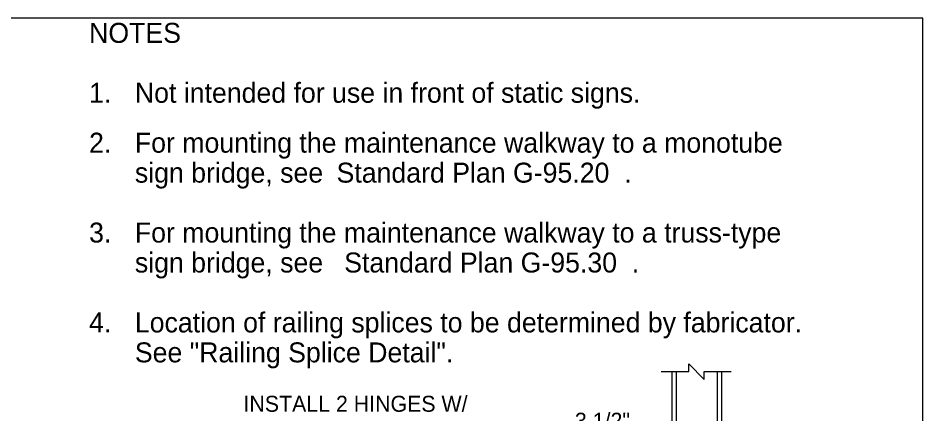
# Model space of a CAD drawing. Extents: x 99862 to 103151, y 100000 to 108076.
# Drawn here: x 102244 to 103151, y 101679 to 102076 of the extents above; entities that cross this region are included whole.
import ezdxf

# ---------------------------------------------------------------- set-up
doc = ezdxf.new("R2010")
doc.units = 0
for name, color, linetype in [('Level 1', 7, 'Continuous'), ('Level 13', 7, 'Continuous'), ('Level 15', 7, 'Continuous'), ('Level 20', 7, 'Continuous'), ('Level 4', 7, 'Continuous'), ('Level 60', 7, 'Continuous')]:
    doc.layers.add(name, color=color, linetype=linetype)

msp = doc.modelspace()

# ---------------------------------------------------------------- linework, layer by layer
at = {"layer": 'Level 1'}
msp.add_lwpolyline([(99862, 99999.5), (103151, 99999.5), (103151, 102075.5), (99862, 102075.5)], close=True, dxfattribs=at)
at = {"layer": 'Level 13'}
for p, q in [((102899.33, 101721.47), (102899.33, 101122.28)), ((102949.33, 101122.28), (102949.33, 101721.47))]:
    msp.add_line(p, q, dxfattribs=at)
at = {"layer": 'Level 15'}
msp.add_lwpolyline([(102888.69, 101721.47), (102916.27, 101721.47), (102916.27, 101729.21), (102931.76, 101713.73), (102931.76, 101721.47), (102958.68, 101721.47)], dxfattribs=at)
at = {"layer": 'Level 4'}
for p, q in [((102903.88, 101122.28), (102903.88, 101721.47)), ((102944.79, 101721.47), (102944.79, 101122.28))]:
    msp.add_line(p, q, dxfattribs=at)
at = {"layer": 'Level 60'}
msp.add_line((103151, 102075.5), (103151, 102075.5), dxfattribs=at)

# ---------------------------------------------------------------- texts
at = {"layer": 'Level 20'}
for s, height, p in [('NOTES', 20, (102314.91, 102050.74)), ('1.', 20, (102314.91, 101990.74)), ('Not intended for use in front of static signs.', 20, (102360.82, 101990.74)), ('2.', 20, (102314.91, 101940.74)), ('For mounting the maintenance walkway to a monotube', 20, (102360.82, 101940.74)), ('sign bridge, see', 20, (102360.82, 101910.74)), (' Standard Plan G-95.20', 20, (102555.62, 101910.74)), ('.', 20, (102851.54, 101910.74)), ('3.', 20, (102314.91, 101850.74)), ('For mounting the maintenance walkway to a truss-type', 20, (102360.82, 101850.74)), ('sign bridge, see ', 20, (102360.82, 101820.74)), ('Standard Plan G-95.30', 20, (102570.73, 101820.74)), ('.', 20, (102859.1, 101820.74)), ('4.', 20, (102314.91, 101760.74)), ('Location of railing splices to be determined by fabricator.', 20, (102360.82, 101760.74)), ('See "Railing Splice Detail".', 20, (102360.82, 101730.74)), ('INSTALL 2 HINGES W/', 16, (102469.71, 101681.27)), ('3 1/2" ', 16, (102802.09, 101664.31))]:
    msp.add_text(s, height=height, dxfattribs=at).set_placement(p)

doc.saveas('drawing.dxf')
